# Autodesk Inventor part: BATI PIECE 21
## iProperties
Created: 2004-11
Part Number: BATI PIECE 21
Document SubType Name: Modeling
Designer: Bruno
Manufacturer: Standard
Standards Organization: Custom
Author: Bruno
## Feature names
1. Base1
